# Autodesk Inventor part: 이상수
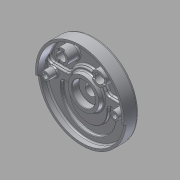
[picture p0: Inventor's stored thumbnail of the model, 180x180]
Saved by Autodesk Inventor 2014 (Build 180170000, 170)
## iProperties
Created: 2015-05
Part Number: 이상수
Material: 알루미늄 6061
Document SubType Name: Modeling
Designer: USER
Density: 2.71 g/cm^3
Appearance: 알루미늄 - 평지
Mass: 1091.66 g
Surface Area: 1039.9 cm^2
Volume: 402.825 cm^3
Author: USER
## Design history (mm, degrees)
sketch "스케치1"
  geometry: C1 r 95 at (0, 0); 1 further point
  constraints: 1 centre point, 1 coincident
  dimensions: "d0" = 190 diameter of C1
extrude "돌출1" new body sketch "스케치1" distance "d1" = 32; taper "d2" = 0 deg
sketch "스케치2"
  geometry: L1 (0, 0)-(-94.638, -8.28); L2 (0, 0)-(94.638, -8.28); L3 (-90, 0)-(90, 0); A1 r 95 centre (0, 0) between (94.638, -8.28) and (-94.638, -8.28) reference
  constraints: 6 end point, 2 point on circle, 1 coincident, 1 horizontal, 1 midpoint
  dimensions: "d4" = 5 deg angle of L2 L3; "d5" = 5 deg angle of L1 L3
extrude "돌출2" cut sketch "스케치2" distance "d6" = 5; taper "d7" = 0 deg
sketch "스케치3"
  geometry: C1 r 95 at (0, 0) reference; C2 r 25 at (0, 0)
  constraints: 1 centre point, 1 coincident
  dimensions: "d8" = 50 diameter of C2
extrude "돌출3" join sketch "스케치3" distance "d9" = 12; taper "d10" = -15 deg
sketch "스케치4"
  geometry: L1 (-89.196, 12)-(-40.249, 12); L2 (40.249, 12)-(89.196, 12); A1 r 95 centre (0, 0) between (94.638, -8.28) and (-94.638, -8.28) reference; A2 r 42 centre (0, 0) between (40.249, 12) and (-40.249, 12); A3 r 90 centre (0, 0) between (89.196, 12) and (-89.196, 12); 1 further point
  constraints: 4 end point, 4 point on circle, 2 centre point, 2 coincident, 2 horizontal
  dimensions: "d11" = 84 diameter of A2; "d12" = 180 diameter of A3; "d14" = 12 distance from line of point (0, 0) L2; "d15" = 12 distance from line of point (0, 0) L1
extrude "돌출4" cut sketch "스케치4" distance "d16" = 25; taper "d17" = 0 deg
fillet "모깎기1" dims "d18" = 10
sketch "스케치5"
  geometry: L1 (-47.117, 12)-(-76.916, 12) reference; L2 (76.916, 12)-(47.117, 12) reference; C1 r 42 at (0, 0); C2 r 90 at (0, 0); A1 r 42 centre (0, 0) between (38.056, 17.769) and (-38.056, 17.769) reference; A2 r 10 centre (-47.117, 22) between (-47.117, 12) and (-38.056, 17.769) reference; A3 r 10 centre (-76.916, 22) between (-86.53, 24.75) and (-76.916, 12) reference; A4 r 90 centre (0, 0) between (86.53, 24.75) and (-86.53, 24.75) reference; A5 r 10 centre (76.916, 22) between (76.916, 12) and (86.53, 24.75) reference; A6 r 10 centre (47.117, 22) between (38.056, 17.769) and (47.117, 12) reference; A7 r 95 centre (0, 0) between (94.638, -8.28) and (-94.638, -8.28) reference
  constraints: 2 centre point, 2 coincident
  dimensions: "d19" = 84 diameter of C1; "d20" = 180 diameter of C2
extrude "돌출5" cut sketch "스케치5" distance "d21" = 18; taper "d22" = 0 deg
sketch "스케치7"
  geometry: C1 r 15 at (-40, 52); C2 r 15 at (40, 52); A1 r 90 centre (0, 0) between (86.53, 24.75) and (-86.53, 24.75) reference
  constraints: 2 centre point, 1 equal radius, 1 horizontal alignment
  dimensions: "d23" = 30 diameter of C1; "d24" = 40 horizontal distance of C1.centre A1.centre; "d25" = 80 distance of C2.centre C1.centre; "d26" = 52 vertical distance of A1.centre C1.centre
extrude "돌출6" join sketch "스케치7" distance "d27" = 25; taper "d28" = 0 deg
sketch "스케치8"
  geometry: C1 r 15 at (-40, -52) reference; C2 r 15 at (40, -52) reference; C3 r 10 at (40, -52); C4 r 10 at (-40, -52)
  constraints: 2 centre point, 2 coincident
  dimensions: "d29" = 20 diameter of C3; "d30" = 20 diameter of C4
extrude "돌출7" cut sketch "스케치8" stored distance "d31" = 0; taper "d32" = 0 deg
sketch "스케치9"
  geometry: L1 (-6, 13.748)-(-6, -13.748); L2 (6, 13.748)-(6, -13.748); L3 (66.252, 6)-(93.748, 6); L4 (66.252, -6)-(93.748, -6); C1 r 10 at (0, 0) reference; C2 r 10 at (80, 0) reference; A1 r 15 centre (0, 0) between (-6, 13.748) and (6, 13.748) reference; A2 r 15 centre (80, 0) between (93.748, 6) and (93.748, -6) reference; 1 further point
  constraints: 8 end point, 8 point on circle, 2 parallel, 1 perpendicular, 1 vertical
  dimensions: "d33" = 6 distance from line of C1.centre L1; "d34" = 12 distance between parallel lines of L2 L1; "d35" = 6 distance from line of L3 C2.centre; "d36" = 12 distance between parallel lines of L4 L3
extrude "돌출8" cut sketch "스케치9" distance "d37" = 3; taper "d38" = 0 deg
sketch "스케치10"
  geometry: C1 r 25 at (0, 0) reference; C2 r 9 at (74, 0); C3 r 9 at (-74, 0)
  constraints: 2 centre point, 2 horizontal alignment, 1 equal radius
  dimensions: "d39" = 18 diameter of C2; "d40" = 148 distance of C3.centre C2.centre; "d41" = 74 distance of C3.centre C1.centre
extrude "돌출9" join sketch "스케치10" distance "d42" = 32; taper "d43" = 0 deg
sketch "스케치11"
  geometry: C1 r 9 at (74, 0) reference; C2 r 9 at (-74, 0) reference; 2 further points
  constraints: 2 coincident
hole "구멍1" sketch "스케치11" at (74, 0), (-74, 0) diameter "d44" = 11; stored, may be unused: countersink angle "d48" = 90 deg, drill point angle "d50" = 118 deg; dims "d45" = 6, "d46" = 18, "d47" = 11, "d49" = 8
sketch "스케치12"
  geometry: C1 r 42 at (0, 0); A1 r 90 centre (0, 0) between (-86.53, 24.75) and (86.53, 24.75) reference
  constraints: 1 centre point, 1 coincident
  dimensions: "d51" = 84 diameter of C1
extrude "돌출10" cut sketch "스케치12" stored distance "d52" = 0; taper "d53" = 0 deg
sketch "스케치13"
  geometry: C1 r 35 at (0, 0); A1 r 90 centre (0, 0) between (-86.53, 24.75) and (86.53, 24.75) reference
  constraints: 1 centre point, 1 coincident
  dimensions: "d54" = 70 diameter of C1
extrude "돌출11" join sketch "스케치13" distance "d55" = 10; taper "d56" = -10 deg
sketch "스케치14"
  geometry: C1 r 33.237 at (0, 0) reference; 1 further point
  constraints: 1 coincident
hole "구멍2" sketch "스케치14" at (0, 0) diameter "d57" = 23; stored, may be unused: countersink angle "d61" = 90 deg, drill point angle "d63" = 118 deg; dims "d58" = 6, "d59" = 50, "d60" = 15, "d62" = 8
sketch "스케치15"
  geometry: L1 (-76.916, 12)-(-47.117, 12) reference; L2 (-50, -19)-(-50, -14); L3 (50, -19)-(50, -14); L4 (-59, -19)-(-59, -14); L5 (-41, -19)-(-41, -14); L6 (41, -19)-(41, -14); L7 (59, -19)-(59, -14); A1 r 35 centre (0, 0) between (-25.426, 24.053) and (25.426, 24.053) reference; A2 r 41 centre (0, -19) between (-41, -19) and (41, -19); A3 r 59 centre (0, -19) between (-59, -19) and (59, -19); A4 r 50 centre (0, -19) between (-50, -19) and (50, -19); A5 r 50 centre (0, -19) between (25.426, 24.053) and (-25.426, 24.053); A6 r 9 centre (50, -14) between (59, -14) and (41, -14); A7 r 9 centre (-50, -14) between (-41, -14) and (-59, -14); 3 further points
  constraints: 14 point on circle, 12 end point, 6 centre point, 6 tangent, 5 coincident, 3 parallel, 1 horizontal, 1 vertical, 1 vertical alignment, 10 other
  dimensions: "d65" = 19 dimension on A1.centre; "d68" = 41 radius of A2; "d69" = 59 radius of A3; "d72" = 50 radius of A4; "d73" = 5 distance of L2.start L2.end; "d74" = 5 distance of L3.start L3.end; "d75" = 18 diameter of A6; "d76" = 18 diameter of A7
extrude "돌출12" cut sketch "스케치15" distance "d77" = 7; taper "d78" = 0 deg
fillet "모깎기2" dims "d79" = 3
fillet "모깎기3" dims "d80" = 3
fillet "모깎기4" dims "d81" = 1
fillet "모깎기5" dims "d82" = 0.3
fillet "모깎기6" dims "d83" = 3
fillet "모깎기7" dims "d84" = 5
fillet "모깎기8" dims "d85" = 3
fillet "모깎기11" dims "d98" = 3
chamfer "모따기1" distance "d99" = 1; stored, may be unused: second distance "d100" = 2, angle "d101" = 45 deg
chamfer "모따기2" distance "d102" = 1; stored, may be unused: second distance "d103" = 2, angle "d104" = 45 deg
sketch "스케치23"
  geometry: L1 (0, 0)-(0, 97.892); L2 (0, 0)-(-36.062, 36.062); L3 (-36.062, 36.062)-(-50.912, 50.912); L4 (0, 0)-(36.062, 36.062); L5 (36.062, 36.062)-(50.912, 50.912); C1 r 90 at (0, 0) reference; C2 r 27.302 at (0, 0) reference; A1 r 51 centre (0, 0) between (36.062, 36.062) and (-36.062, 36.062); A2 r 72 centre (0, 0) between (50.912, 50.912) and (-50.912, 50.912); 1 further point
  constraints: 10 end point, 5 point on circle, 2 centre point, 2 coincident, 2 collinear, 1 vertical, 1 vertical alignment
  dimensions: "d135" = 90 deg angle of L2 L4; "d136" = 51 radius of A1; "d137" = 72 radius of A2
extrude "돌출15" join sketch "스케치23" distance "d138" = 5; taper "d139" = 0 deg
fillet "모깎기21" dims "d140" = 5
fillet "모깎기22" dims "d141" = 5, "d142" = 3
sketch "스케치24"
  geometry: C1 r 68 at (0, 0); A1 r 56 centre (0, 0) between (35.904, 42.975) and (-35.904, 42.975) reference
  constraints: 1 centre point, 1 coincident, 1 other
  dimensions: "d143" = 136 diameter of C1
feature "엠보싱5" sketch "스케치24" dims "d144" = 0.5, "d145" = 0
node "솔리드1"
node "투영된 루프1"
other parameters: "d13" = 12, "d66" = 82, "d67" = 118, "d86" = 144
